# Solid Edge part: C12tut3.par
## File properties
Author: CADCIM
Template: ansi part.par
Last saved by: CADCIM
Revision: 6
Application: Solid Edge
Accuracy: 0.990
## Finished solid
Body 1: solid body, 13 faces, 19 edges, 8 vertices.
  Faces by surface: plane 9, cylinder 4
  Edges by curve: line 10, circle 8, ellipse 1
Bounding box of the edges (mm): 31.750 x 82.544 x 31.750, from (-15.875, -77.8163, -15.875) to (15.875, 4.7283, 15.875).
Cylindrical faces by radius (mm): R5.5944 x1, R6.35 x1, R7.9375 x1, R15.875 x1
Planar faces by outward normal: +x 1, +y 1, +z 1, -x 1, -y 4, oblique 1
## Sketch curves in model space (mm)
line (-22.2359, -0.0325, 12.7) -> (-22.2334, -4.7925, 7.935)
line (-22.2322, -77.8163, 5.5531) -> (-22.2323, -0.0289, 5.77)
line (-22.2262, -77.8103, -5.6356) -> (-22.2263, -0.0229, -5.5751)
line (-22.2326, -68.2917, 6.3138) -> (-22.2326, -77.8167, 6.3087)
line (-22.2326, -77.8167, 6.3087) -> (-22.2258, -77.8099, -6.3913)
line (-22.2258, -68.2849, -6.3862) -> (-22.2258, -77.8099, -6.3913)
line (-22.2376, -0.0342, 15.875) -> (-22.2208, -0.0174, -15.875)
line (-22.2376, 4.7283, 15.8775) -> (-22.2376, -0.0342, 15.875)
line (-22.2376, 4.7283, 15.8775) -> (-22.2208, 4.7451, -15.8725)
line (-22.2208, 4.7451, -15.8725) -> (-22.2208, -0.0174, -15.875)
line (-22.225, -0.0216, -7.9375) -> (-22.225, -68.2841, -7.9737)
line (-22.2334, -0.03, 7.9375) -> (-22.2334, -68.2925, 7.9013)
line (-22.2334, -68.2925, 7.9013) -> (-22.225, -68.2841, -7.9737)
line (0, 0, 22.225) -> (0, 0, -22.225)
line (22.225, 0, 0) -> (-22.225, 0, 0)
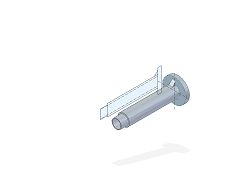
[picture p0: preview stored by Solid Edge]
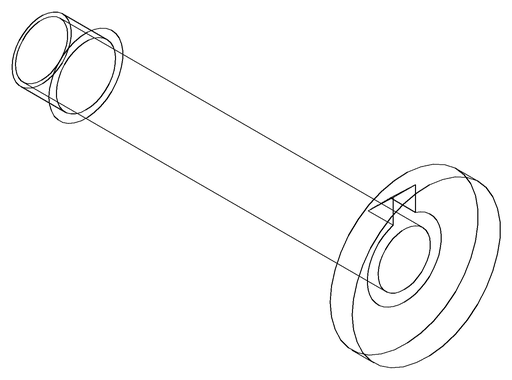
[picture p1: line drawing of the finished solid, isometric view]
